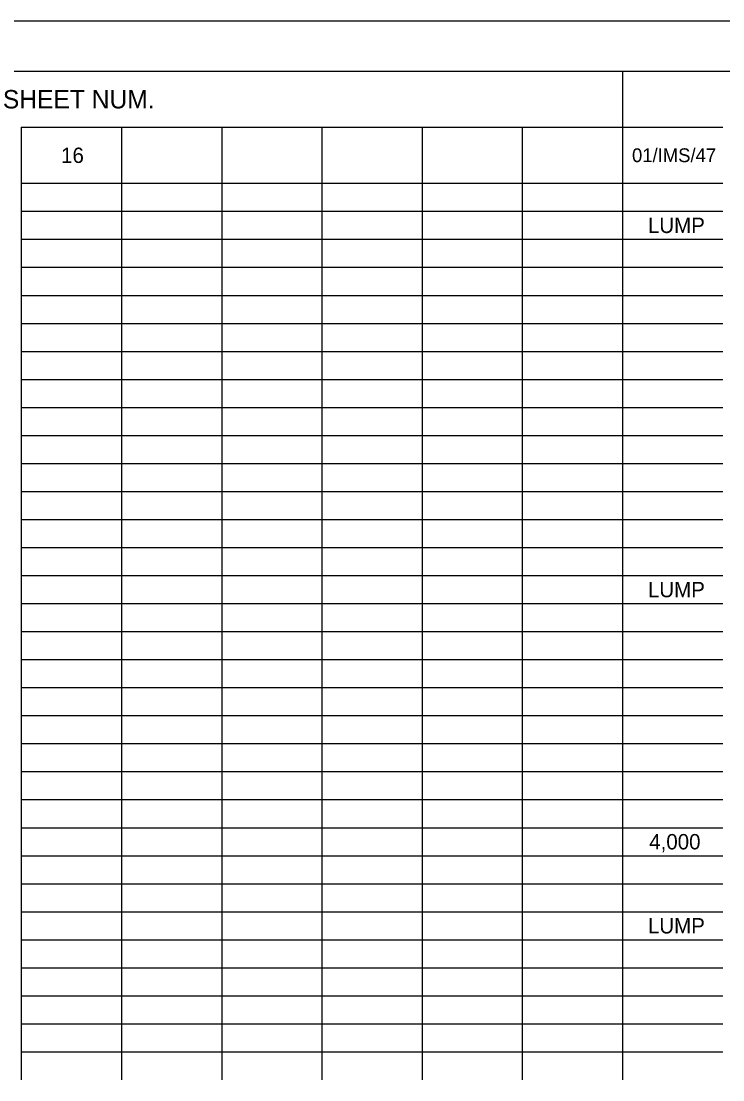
# Model space of a CAD drawing. Extents: x 0 to 34, y 0 to 22.
# Drawn here: x 6.51 to 13.53, y 11.42 to 22 of the extents above; entities that cross this region are included whole.
import ezdxf

# ---------------------------------------------------------------- set-up
doc = ezdxf.new("R2010")
doc.units = 0
for name, color, linetype in [('SH_Border', 7, 'Continuous'), ('SH_Cut_Line', 7, 'Continuous'), ('SH_Text', 7, 'Continuous')]:
    doc.layers.add(name, color=color, linetype=linetype)

msp = doc.modelspace()

# ---------------------------------------------------------------- linework, layer by layer
at = {"layer": 'SH_Border'}
msp.add_lwpolyline([(1.5, 21.5), (33.5, 21.5), (33.5, 0.5), (1.5, 0.5)], close=True, dxfattribs=at)
at = {"layer": 'SH_Cut_Line'}
msp.add_lwpolyline([(0, 0), (34, 0), (34, 22), (0, 22)], close=True, dxfattribs=at)
at = {"layer": 'SH_Text'}
for p, q in [((6.513, 21.5), (7.515, 21.5)), ((7.515, 21.5), (12.528, 21.5)), ((12.528, 21.5), (13.53, 21.5)), ((12.528, 21.5), (12.528, 21.22)), ((12.528, 21.22), (12.528, 20.94)), ((6.513, 20.94), (7.515, 20.94)), ((6.513, 20.94), (6.513, 20.66)), ((7.515, 20.94), (12.528, 20.94)), ((7.515, 20.94), (7.515, 20.66)), ((8.518, 20.94), (8.518, 20.66)), ((9.52, 20.94), (9.52, 20.66)), ((10.523, 20.94), (10.523, 20.66)), ((11.525, 20.94), (11.525, 20.66)), ((12.528, 20.94), (13.53, 20.94)), ((12.528, 20.94), (12.528, 20.66)), ((6.513, 20.66), (6.513, 20.38)), ((7.515, 20.66), (7.515, 20.38)), ((8.518, 20.66), (8.518, 20.38)), ((9.52, 20.66), (9.52, 20.38)), ((10.523, 20.66), (10.523, 20.38)), ((11.525, 20.66), (11.525, 20.38)), ((12.528, 20.66), (12.528, 20.38)), ((6.513, 20.38), (7.515, 20.38)), ((6.513, 20.38), (6.513, 20.1)), ((7.515, 20.38), (12.528, 20.38)), ((7.515, 20.38), (7.515, 20.1)), ((8.518, 20.38), (8.518, 20.1)), ((9.52, 20.38), (9.52, 20.1)), ((10.523, 20.38), (10.523, 20.1)), ((11.525, 20.38), (11.525, 20.1)), ((12.528, 20.38), (13.53, 20.38)), ((12.528, 20.38), (12.528, 20.1)), ((6.513, 20.1), (7.515, 20.1)), ((6.513, 20.1), (6.513, 18.7)), ((7.515, 20.1), (12.528, 20.1)), ((7.515, 20.1), (7.515, 18.7)), ((8.518, 20.1), (8.518, 18.7)), ((9.52, 20.1), (9.52, 18.7)), ((10.523, 20.1), (10.523, 18.7)), ((11.525, 20.1), (11.525, 18.7)), ((12.528, 20.1), (13.53, 20.1)), ((12.528, 20.1), (12.528, 18.7)), ((6.513, 19.82), (7.515, 19.82)), ((7.515, 19.82), (12.528, 19.82)), ((12.528, 19.82), (13.53, 19.82)), ((6.513, 19.54), (7.515, 19.54)), ((7.515, 19.54), (12.528, 19.54)), ((12.528, 19.54), (13.53, 19.54)), ((6.513, 19.26), (7.515, 19.26)), ((7.515, 19.26), (12.528, 19.26)), ((12.528, 19.26), (13.53, 19.26)), ((6.513, 18.98), (7.515, 18.98)), ((7.515, 18.98), (12.528, 18.98)), ((12.528, 18.98), (13.53, 18.98)), ((6.513, 18.7), (7.515, 18.7)), ((6.513, 18.7), (6.513, 18.14)), ((7.515, 18.7), (12.528, 18.7)), ((7.515, 18.7), (7.515, 18.14)), ((8.518, 18.7), (8.518, 18.14)), ((9.52, 18.7), (9.52, 18.14)), ((10.523, 18.7), (10.523, 18.14)), ((11.525, 18.7), (11.525, 18.14)), ((12.528, 18.7), (13.53, 18.7)), ((12.528, 18.7), (12.528, 18.14)), ((6.513, 18.42), (7.515, 18.42)), ((7.515, 18.42), (12.528, 18.42)), ((12.528, 18.42), (13.53, 18.42)), ((6.513, 18.14), (7.515, 18.14)), ((6.513, 18.14), (6.513, 17.86)), ((7.515, 18.14), (12.528, 18.14)), ((7.515, 18.14), (7.515, 17.86)), ((8.518, 18.14), (8.518, 17.86)), ((9.52, 18.14), (9.52, 17.86)), ((10.523, 18.14), (10.523, 17.86)), ((11.525, 18.14), (11.525, 17.86)), ((12.528, 18.14), (13.53, 18.14)), ((12.528, 18.14), (12.528, 17.86)), ((6.513, 17.86), (7.515, 17.86)), ((6.513, 17.86), (6.513, 17.58)), ((7.515, 17.86), (12.528, 17.86)), ((7.515, 17.86), (7.515, 17.58)), ((8.518, 17.86), (8.518, 17.58)), ((9.52, 17.86), (9.52, 17.58)), ((10.523, 17.86), (10.523, 17.58)), ((11.525, 17.86), (11.525, 17.58)), ((12.528, 17.86), (13.53, 17.86)), ((12.528, 17.86), (12.528, 17.58)), ((6.513, 17.58), (7.515, 17.58)), ((6.513, 17.58), (6.513, 17.3)), ((7.515, 17.58), (12.528, 17.58)), ((7.515, 17.58), (7.515, 17.3)), ((8.518, 17.58), (8.518, 17.3)), ((9.52, 17.58), (9.52, 17.3)), ((10.523, 17.58), (10.523, 17.3)), ((11.525, 17.58), (11.525, 17.3)), ((12.528, 17.58), (13.53, 17.58)), ((12.528, 17.58), (12.528, 17.3)), ((6.513, 17.3), (7.515, 17.3)), ((6.513, 17.3), (6.513, 17.02)), ((7.515, 17.3), (12.528, 17.3)), ((7.515, 17.3), (7.515, 17.02)), ((8.518, 17.3), (8.518, 17.02)), ((9.52, 17.3), (9.52, 17.02)), ((10.523, 17.3), (10.523, 17.02)), ((11.525, 17.3), (11.525, 17.02)), ((12.528, 17.3), (13.53, 17.3)), ((12.528, 17.3), (12.528, 17.02)), ((6.513, 17.02), (7.515, 17.02)), ((6.513, 17.02), (6.513, 16.74)), ((7.515, 17.02), (12.528, 17.02)), ((7.515, 17.02), (7.515, 16.74)), ((8.518, 17.02), (8.518, 16.74)), ((9.52, 17.02), (9.52, 16.74)), ((10.523, 17.02), (10.523, 16.74)), ((11.525, 17.02), (11.525, 16.74)), ((12.528, 17.02), (13.53, 17.02)), ((12.528, 17.02), (12.528, 16.74)), ((6.513, 16.74), (7.515, 16.74)), ((6.513, 16.74), (6.513, 16.18)), ((7.515, 16.74), (12.528, 16.74)), ((7.515, 16.74), (7.515, 16.18)), ((8.518, 16.74), (8.518, 16.18)), ((9.52, 16.74), (9.52, 16.18)), ((10.523, 16.74), (10.523, 16.18)), ((11.525, 16.74), (11.525, 16.18)), ((12.528, 16.74), (13.53, 16.74)), ((12.528, 16.74), (12.528, 16.18)), ((6.513, 16.46), (7.515, 16.46)), ((7.515, 16.46), (12.528, 16.46)), ((12.528, 16.46), (13.53, 16.46)), ((6.513, 16.18), (7.515, 16.18)), ((6.513, 16.18), (6.513, 15.9)), ((7.515, 16.18), (12.528, 16.18)), ((7.515, 16.18), (7.515, 15.9)), ((8.518, 16.18), (8.518, 15.9)), ((9.52, 16.18), (9.52, 15.9)), ((10.523, 16.18), (10.523, 15.9)), ((11.525, 16.18), (11.525, 15.9)), ((12.528, 16.18), (13.53, 16.18)), ((12.528, 16.18), (12.528, 15.9)), ((6.513, 15.9), (7.515, 15.9)), ((6.513, 15.9), (6.513, 15.62)), ((7.515, 15.9), (12.528, 15.9)), ((7.515, 15.9), (7.515, 15.62)), ((8.518, 15.9), (8.518, 15.62)), ((9.52, 15.9), (9.52, 15.62)), ((10.523, 15.9), (10.523, 15.62)), ((11.525, 15.9), (11.525, 15.62)), ((12.528, 15.9), (13.53, 15.9)), ((12.528, 15.9), (12.528, 15.62)), ((6.513, 15.62), (7.515, 15.62)), ((6.513, 15.62), (6.513, 15.34)), ((7.515, 15.62), (12.528, 15.62)), ((7.515, 15.62), (7.515, 15.34)), ((8.518, 15.62), (8.518, 15.34)), ((9.52, 15.62), (9.52, 15.34)), ((10.523, 15.62), (10.523, 15.34)), ((11.525, 15.62), (11.525, 15.34)), ((12.528, 15.62), (13.53, 15.62)), ((12.528, 15.62), (12.528, 15.34)), ((6.513, 15.34), (7.515, 15.34)), ((6.513, 15.34), (6.513, 14.78)), ((7.515, 15.34), (12.528, 15.34)), ((7.515, 15.34), (7.515, 14.78)), ((8.518, 15.34), (8.518, 14.78)), ((9.52, 15.34), (9.52, 14.78)), ((10.523, 15.34), (10.523, 14.78)), ((11.525, 15.34), (11.525, 14.78)), ((12.528, 15.34), (13.53, 15.34)), ((12.528, 15.34), (12.528, 14.78)), ((6.513, 15.06), (7.515, 15.06)), ((7.515, 15.06), (12.528, 15.06)), ((12.528, 15.06), (13.53, 15.06)), ((6.513, 14.78), (7.515, 14.78)), ((6.513, 14.78), (6.513, 14.5)), ((7.515, 14.78), (12.528, 14.78)), ((7.515, 14.78), (7.515, 14.5)), ((8.518, 14.78), (8.518, 14.5)), ((9.52, 14.78), (9.52, 14.5)), ((10.523, 14.78), (10.523, 14.5)), ((11.525, 14.78), (11.525, 14.5)), ((12.528, 14.78), (13.53, 14.78)), ((12.528, 14.78), (12.528, 14.5)), ((6.513, 14.5), (7.515, 14.5)), ((6.513, 14.5), (6.513, 14.22)), ((7.515, 14.5), (12.528, 14.5)), ((7.515, 14.5), (7.515, 14.22)), ((8.518, 14.5), (8.518, 14.22)), ((9.52, 14.5), (9.52, 14.22)), ((10.523, 14.5), (10.523, 14.22)), ((11.525, 14.5), (11.525, 14.22)), ((12.528, 14.5), (13.53, 14.5)), ((12.528, 14.5), (12.528, 14.22)), ((6.513, 14.22), (7.515, 14.22)), ((6.513, 14.22), (6.513, 13.94)), ((7.515, 14.22), (12.528, 14.22)), ((7.515, 14.22), (7.515, 13.94)), ((8.518, 14.22), (8.518, 13.94)), ((9.52, 14.22), (9.52, 13.94)), ((10.523, 14.22), (10.523, 13.94)), ((11.525, 14.22), (11.525, 13.94)), ((12.528, 14.22), (13.53, 14.22)), ((12.528, 14.22), (12.528, 13.94)), ((6.513, 13.94), (7.515, 13.94)), ((6.513, 13.94), (6.513, 11.7)), ((7.515, 13.94), (12.528, 13.94)), ((7.515, 13.94), (7.515, 11.7)), ((8.518, 13.94), (8.518, 11.7)), ((9.52, 13.94), (9.52, 11.7)), ((10.523, 13.94), (10.523, 11.7)), ((11.525, 13.94), (11.525, 11.7)), ((12.528, 13.94), (13.53, 13.94)), ((12.528, 13.94), (12.528, 11.7)), ((6.513, 13.66), (7.515, 13.66)), ((7.515, 13.66), (12.528, 13.66)), ((12.528, 13.66), (13.53, 13.66)), ((6.513, 13.38), (7.515, 13.38)), ((7.515, 13.38), (12.528, 13.38)), ((12.528, 13.38), (13.53, 13.38)), ((6.513, 13.1), (7.515, 13.1)), ((7.515, 13.1), (12.528, 13.1)), ((12.528, 13.1), (13.53, 13.1)), ((6.513, 12.82), (7.515, 12.82)), ((7.515, 12.82), (12.528, 12.82)), ((12.528, 12.82), (13.53, 12.82)), ((6.513, 12.54), (7.515, 12.54)), ((7.515, 12.54), (12.528, 12.54)), ((12.528, 12.54), (13.53, 12.54)), ((6.513, 12.26), (7.515, 12.26)), ((7.515, 12.26), (12.528, 12.26)), ((12.528, 12.26), (13.53, 12.26)), ((6.513, 11.98), (7.515, 11.98)), ((7.515, 11.98), (12.528, 11.98)), ((12.528, 11.98), (13.53, 11.98)), ((6.513, 11.7), (7.515, 11.7)), ((6.513, 11.7), (6.513, 11.42)), ((7.515, 11.7), (12.528, 11.7)), ((7.515, 11.7), (7.515, 11.42)), ((8.518, 11.7), (8.518, 11.42)), ((9.52, 11.7), (9.52, 11.42)), ((10.523, 11.7), (10.523, 11.42)), ((11.525, 11.7), (11.525, 11.42)), ((12.528, 11.7), (13.53, 11.7)), ((12.528, 11.7), (12.528, 11.42))]:
    msp.add_line(p, q, dxfattribs=at)

# ---------------------------------------------------------------- texts
for s, height, p in [('SHEET NUM.', 0.184, (6.33, 21.128)), ('16', 0.1533, (6.912, 20.583)), ('01/IMS/47', 0.138, (12.622, 20.591)), ('LUMP', 0.1533, (12.781, 19.883)), ('LUMP', 0.1533, (12.781, 16.243)), ('4,000', 0.1533, (12.794, 13.723)), ('LUMP', 0.1533, (12.781, 12.883))]:
    msp.add_text(s, height=height, dxfattribs=at).set_placement(p)

doc.saveas('drawing.dxf')
